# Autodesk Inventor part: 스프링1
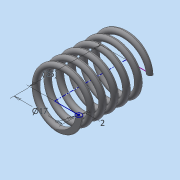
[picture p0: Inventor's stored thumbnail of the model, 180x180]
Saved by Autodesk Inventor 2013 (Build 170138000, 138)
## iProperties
Created: 2019-07
Part Number: 스프링1
Material: 일반
Document SubType Name: Modeling
Designer: dgall
Density: 1 g/cm^3
Mass: -0.0170894 g
Surface Area: 20.0756 cm^2
Volume: -0.0170894 cm^3
Author: dgall
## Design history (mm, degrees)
sketch "스케치1"
  geometry: L1 (8.5, 0)-(0, 0); L2 (0, 0)-(0, 25.33); L3 (0, 25.33)-(8.5, 25.33); C1 r 1 at (8.5, 0)
  constraints: 6 end point, 2 parallel, 1 centre point, 1 coincident, 1 horizontal, 1 perpendicular
  dimensions: "d0" = 17 diameter of L1.start L2; "d2" = 25.33013 distance of L1.end L2.end (derived); "d3" = 2 diameter of C1
feature "코일1" pitch "d4" = 10; turns "d6" = 6; dims "d5" = 25.33013 (= d2), "d7" = 0, angle "d8" = 90 deg, angle "d9" = 90 deg, "d10" = 0, "d11" = 0
node "작업 평면1"
feature "분할1"
feature "분할2"
node "솔리드1"
